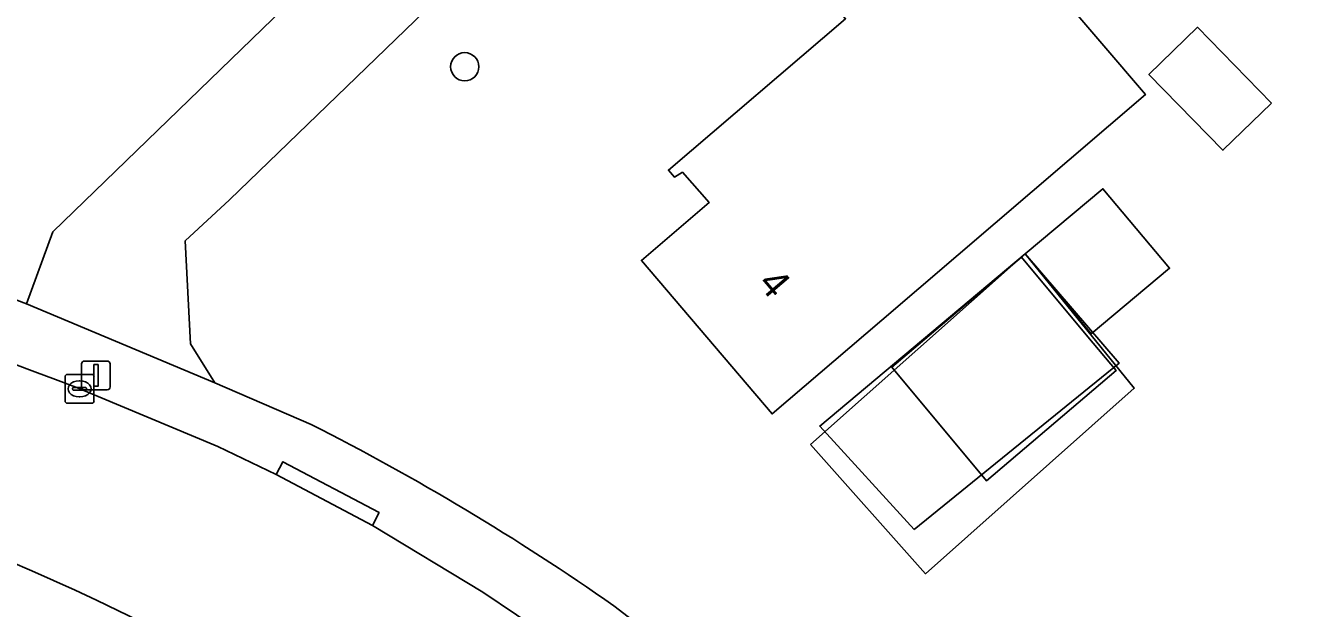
# Model space of a CAD drawing. Extents: x 162879 to 165540, y 384011 to 385181.
# Drawn here: x 163867.39 to 163912.1, y 384222.07 to 384242.28 of the extents above; entities that cross this region are included whole.
import ezdxf

# ---------------------------------------------------------------- set-up
doc = ezdxf.new("R2010")
doc.units = 0
for name, color, linetype in [('IMGEO_Boom', 7, 'Continuous'), ('IMGEO_Erf', 7, 'Continuous'), ('IMGEO_Kolk', 7, 'Continuous'), ('IMGEO_Lichtmast', 7, 'Continuous'), ('IMGEO_Pand', 7, 'Continuous'), ('IMGEO_Pand_nummerreeks', 7, 'Continuous'), ('IMGEO_Pand_vergunning_verleend', 7, 'Continuous'), ('IMGEO_Parkeervlak_open', 7, 'Continuous'), ('IMGEO_Rijbaan_lokaal_open', 7, 'Continuous'), ('IMGEO_Voetpad_open', 7, 'Continuous')]:
    doc.layers.add(name, color=color, linetype=linetype)

msp = doc.modelspace()

# ---------------------------------------------------------------- linework, layer by layer
at = {"layer": 'IMGEO_Boom'}
msp.add_circle((163882.612, 384240.859), 0.489, dxfattribs=at)
at = {"layer": 'IMGEO_Erf'}
for points in [[(163866.598, 384232.945), (163867.411, 384232.628), (163868.325, 384235.136), (163878.501, 384245.001), (163874.755, 384248.868), (163875.923, 384250), (163877.229, 384251.265), (163878.452, 384250), (163880.97, 384247.395), (163887.47, 384253.697), (163883.987, 384257.285), (163881.245, 384260.111), (163881.118, 384260.242), (163884.706, 384263.725)], [(163888.682, 384250), (163874.452, 384236.24), (163872.917, 384234.818), (163873.099, 384231.247), (163873.944, 384229.898), (163877.287, 384228.451)], [(163887.777, 384222.157), (163902.197, 384211.088), (163913.637, 384202.307)]]:
    msp.add_lwpolyline(points, dxfattribs=at)
for points in [[(163901.678, 384245.216), (163906.215, 384239.891), (163897.068, 384232.067), (163893.268, 384228.816), (163888.736, 384234.142), (163891.086, 384236.148), (163890.157, 384237.2), (163889.889, 384237.023), (163889.671, 384237.274), (163895.818, 384242.521), (163894.375, 384244.208), (163899.069, 384248.22)], [(163910.579, 384239.595), (163908.901, 384237.96), (163906.336, 384240.595), (163908.014, 384242.229)], [(163907.052, 384233.867), (163904.337, 384231.589), (163902.043, 384234.365), (163904.737, 384236.626)], [(163905.196, 384230.32), (163900.701, 384226.498), (163897.416, 384230.432), (163901.911, 384234.253), (163904.219, 384231.49)]]:
    msp.add_lwpolyline(points, close=True, dxfattribs=at)
msp.add_arc((163838.259, 384151.516), 86.269, 54.97041, 63.10208, dxfattribs=at)
at = {"layer": 'IMGEO_Kolk'}
for p, q in [((163868.83, 384230.185), (163869.682, 384230.185)), ((163868.755, 384229.259), (163868.755, 384230.111)), ((163869.057, 384229.728), (163869.455, 384229.728)), ((163869.243, 384229.965), (163869.268, 384229.965)), ((163869.756, 384230.111), (163869.756, 384229.259)), ((163869.014, 384229.679), (163869.014, 384229.691)), ((163869.452, 384229.642), (163869.054, 384229.642)), ((163869.266, 384229.405), (163869.241, 384229.405)), ((163869.498, 384229.691), (163869.498, 384229.679)), ((163869.682, 384229.185), (163868.83, 384229.185))]:
    msp.add_line(p, q, dxfattribs=at)
for points in [[(163868.83, 384230.185), (163869.682, 384230.185)], [(163868.755, 384229.259), (163868.755, 384230.111)], [(163869.756, 384230.111), (163869.756, 384229.259)], [(163869.682, 384229.185), (163868.83, 384229.185)]]:
    msp.add_lwpolyline(points, dxfattribs=at)
for centre, radius, start, end in [((163868.832, 384230.109), 0.0765, 91.552, 178.448), ((163868.832, 384230.109), 0.0765, 91.552, 178.448), ((163869.68, 384230.109), 0.0765, 1.552, 88.448), ((163869.68, 384230.109), 0.0765, 1.552, 88.448), ((163869.054, 384229.688), 0.0403, 85.8775, 175.7526), ((163869.459, 384229.69), 0.0386, 1.7309, 96.639), ((163869.051, 384229.678), 0.0366, 178.938, 274.7102), ((163869.455, 384229.685), 0.043, 264.8664, 352.4533), ((163868.832, 384229.261), 0.0765, 181.552, 268.448), ((163868.832, 384229.261), 0.0765, 181.552, 268.448), ((163869.68, 384229.261), 0.0765, 271.552, 358.448), ((163869.68, 384229.261), 0.0765, 271.552, 358.448)]:
    msp.add_arc(centre, radius, start, end, dxfattribs=at)
for centre, major_axis, ratio, start_param, end_param in [((163869.242, 384229.685), (-0.387, 0.002), 0.722429, 4.712389, 7.853982), ((163869.267, 384229.685), (-0.39, 0.002), 0.717154, 1.570796, 4.712389)]:
    msp.add_ellipse(centre, major_axis=major_axis, ratio=ratio, start_param=start_param, end_param=end_param, dxfattribs=at)
at = {"layer": 'IMGEO_Lichtmast'}
for p, q in [((163869.425, 384230.649), (163870.215, 384230.649)), ((163870.215, 384230.649), (163869.425, 384230.649)), ((163869.325, 384229.749), (163869.325, 384230.549)), ((163869.325, 384230.549), (163869.325, 384229.749)), ((163870.315, 384230.549), (163870.315, 384229.749)), ((163870.315, 384229.749), (163870.315, 384230.549)), ((163870.215, 384229.649), (163869.425, 384229.649)), ((163869.425, 384229.649), (163870.215, 384229.649))]:
    msp.add_line(p, q, dxfattribs=at)
msp.add_lwpolyline([(163869.745, 384230.524), (163869.895, 384230.524), (163869.895, 384229.774), (163869.745, 384229.774), (163869.745, 384230.524)], dxfattribs=at)
for centre, start, end in [((163869.425, 384230.549), 90, 180), ((163869.425, 384230.549), 90, 180), ((163870.215, 384230.549), 0, 90), ((163870.215, 384230.549), 360, 90), ((163869.425, 384229.749), 180, 270), ((163869.425, 384229.749), 180, 270), ((163870.215, 384229.749), 270, 0), ((163870.215, 384229.749), 270, 0)]:
    msp.add_arc(centre, 0.1, start, end, dxfattribs=at)
at = {"layer": 'IMGEO_Pand'}
for points in [[(163899.069, 384248.22), (163894.375, 384244.208), (163895.818, 384242.521), (163889.671, 384237.274), (163889.889, 384237.023), (163890.157, 384237.2), (163891.086, 384236.148), (163888.736, 384234.142), (163893.268, 384228.816), (163897.068, 384232.067), (163906.215, 384239.891), (163901.678, 384245.216)], [(163910.579, 384239.595), (163908.014, 384242.229), (163906.336, 384240.595), (163908.901, 384237.96)], [(163904.337, 384231.589), (163907.052, 384233.867), (163904.737, 384236.626), (163902.043, 384234.365)], [(163901.911, 384234.253), (163897.416, 384230.432), (163900.701, 384226.498), (163905.196, 384230.32), (163904.219, 384231.49)]]:
    msp.add_lwpolyline(points, close=True, dxfattribs=at)
at = {"layer": 'IMGEO_Pand_vergunning_verleend'}
for points in [[(163894.602, 384227.751), (163902.043, 384234.365), (163905.828, 384229.705), (163898.586, 384223.268)], [(163898.195, 384224.808), (163894.922, 384228.39), (163902.043, 384234.365), (163905.301, 384230.572)]]:
    msp.add_lwpolyline(points, close=True, dxfattribs=at)
at = {"layer": 'IMGEO_Parkeervlak_open'}
msp.add_arc((163836.209, 384151.273), 78.638, 58.06837, 96.32438, dxfattribs=at)
at = {"layer": 'IMGEO_Rijbaan_lokaal_open'}
msp.add_lwpolyline([(163885.575, 384221.055), (163883.235, 384222.627), (163879.41, 384224.949), (163876.075, 384226.717), (163874.054, 384227.681), (163869.123, 384229.738)], dxfattribs=at)
for centre, radius, start, end in [((163838.744, 384152.23), 83.249, 68.59732, 85.26611), ((163836.209, 384151.273), 78.638, 58.06837, 96.32438)]:
    msp.add_arc(centre, radius, start, end, dxfattribs=at)
at = {"layer": 'IMGEO_Voetpad_open'}
for points in [[(163878.501, 384245.001), (163868.325, 384235.136), (163867.411, 384232.628), (163873.944, 384229.898), (163873.099, 384231.247), (163872.917, 384234.818), (163874.452, 384236.24), (163888.682, 384250)], [(163877.287, 384228.451), (163873.944, 384229.898), (163867.411, 384232.628), (163866.598, 384232.945)], [(163869.123, 384229.738), (163874.054, 384227.681), (163876.075, 384226.717), (163876.309, 384227.158), (163879.644, 384225.39), (163879.41, 384224.949), (163883.235, 384222.627), (163885.575, 384221.055), (163910.141, 384202.273)], [(163912.647, 384201.328), (163913.637, 384202.307), (163902.197, 384211.088), (163887.777, 384222.157)]]:
    msp.add_lwpolyline(points, dxfattribs=at)
msp.add_lwpolyline([(163879.41, 384224.949), (163879.644, 384225.39), (163876.309, 384227.158), (163876.075, 384226.717)], close=True, dxfattribs=at)
for centre, radius, start, end in [((163838.744, 384152.23), 83.249, 68.59732, 85.26611), ((163838.259, 384151.516), 86.269, 54.97041, 63.10208)]:
    msp.add_arc(centre, radius, start, end, dxfattribs=at)

# ---------------------------------------------------------------- texts
at = {"layer": 'IMGEO_Pand_nummerreeks'}
msp.add_text('4', height=1, rotation=310.3951, dxfattribs=at).set_placement((163892.743, 384233.322))

doc.saveas('drawing.dxf')
